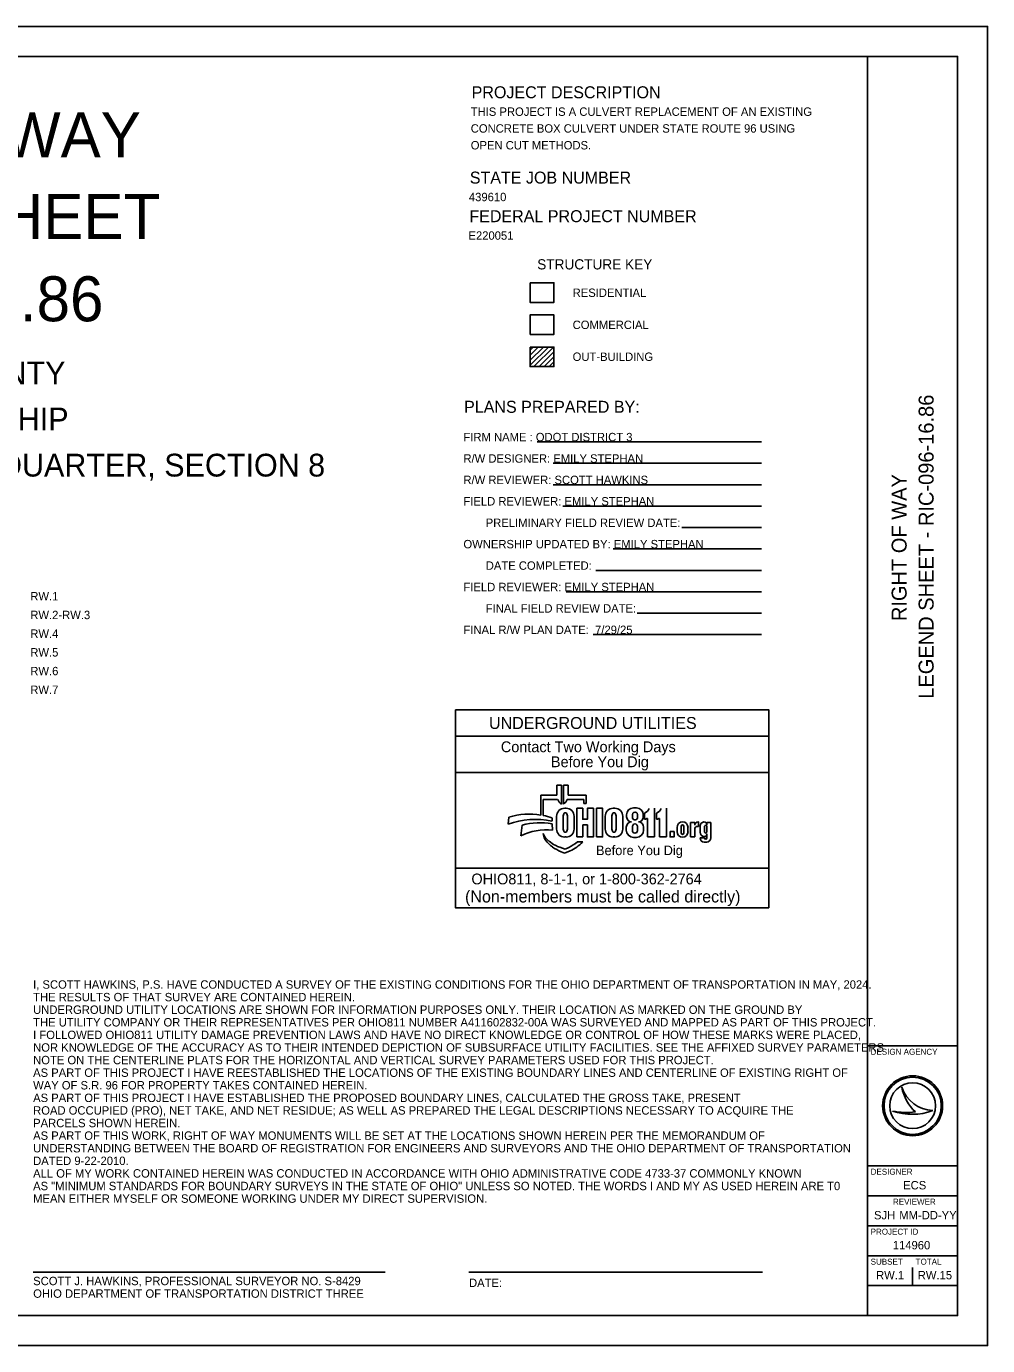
# Model space of a CAD drawing. Extents: x 0 to 34, y 0 to 22.
# Drawn here: x 17.97 to 34, y 0 to 22 of the extents above; entities that cross this region are included whole.
import ezdxf

# ---------------------------------------------------------------- set-up
doc = ezdxf.new("R2010")
doc.units = 0
for name, color, linetype in [('Default', 7, 'Continuous'), ('SC_Shading1', 7, 'Continuous'), ('SH_Border', 7, 'Continuous'), ('SH_Cut_Line', 7, 'Continuous'), ('SH_Data', 7, 'Continuous'), ('SH_Text', 7, 'Continuous')]:
    doc.layers.add(name, color=color, linetype=linetype)

msp = doc.modelspace()

# ---------------------------------------------------------------- linework, layer by layer
at = {"layer": 'Default'}
for p, q in [((18.087, 1.226), (23.954, 1.226)), ((25.349, 1.226), (30.249, 1.226))]:
    msp.add_line(p, q, dxfattribs=at)
at = {"layer": 'SC_Shading1'}
msp.add_lwpolyline([(26.372, 16.863), (26.769, 16.863), (26.769, 17.188), (26.372, 17.188)], close=True, dxfattribs=at)
at = {"layer": 'SH_Border'}
for p, q in [((32, 0.5), (32, 21.5)), ((32, 5), (33.5, 5)), ((32, 3), (33.5, 3)), ((32, 2.5), (33.5, 2.5)), ((32, 2), (33.5, 2)), ((32, 1.5), (33.5, 1.5)), ((32, 1), (33.5, 1))]:
    msp.add_line(p, q, dxfattribs=at)
msp.add_lwpolyline([(1.5, 21.5), (33.5, 21.5), (33.5, 0.5), (1.5, 0.5)], close=True, dxfattribs=at)
at = {"layer": 'SH_Cut_Line'}
msp.add_lwpolyline([(0, 0), (34, 0), (34, 22), (0, 22)], close=True, dxfattribs=at)
at = {"layer": 'SH_Data'}
for p, q in [((26.896, 9.349), (26.816, 9.349)), ((26.816, 9.349), (26.816, 9.182)), ((26.896, 9.032), (26.896, 9.349)), ((27.007, 9.349), (26.927, 9.349)), ((26.927, 9.349), (26.927, 9.032)), ((27.007, 9.182), (27.007, 9.349)), ((26.816, 9.182), (26.553, 9.182)), ((26.553, 9.182), (26.553, 8.848)), ((26.59, 8.841), (26.59, 9.105)), ((26.59, 9.105), (26.831, 9.105)), ((26.991, 9.105), (27.27, 9.105)), ((27.304, 9.182), (27.007, 9.182)), ((27.27, 9.105), (27.27, 9.042)), ((27.27, 9.042), (27.304, 9.042)), ((27.304, 9.042), (27.304, 9.182)), ((26.018, 8.814), (26.004, 8.697)), ((26.737, 8.746), (26.737, 8.804)), ((26.814, 8.827), (26.814, 8.615)), ((26.923, 8.632), (26.923, 8.815)), ((26.972, 8.961), (26.948, 8.961)), ((26.997, 8.815), (26.997, 8.632)), ((27.106, 8.615), (27.106, 8.827)), ((27.25, 8.96), (27.149, 8.96)), ((27.149, 8.96), (27.149, 8.482)), ((27.625, 8.827), (27.625, 8.615)), ((27.734, 8.632), (27.734, 8.815)), ((27.783, 8.961), (27.758, 8.961)), ((27.808, 8.815), (27.808, 8.632)), ((27.917, 8.615), (27.917, 8.827)), ((27.981, 8.854), (27.981, 8.817)), ((28.08, 8.8), (28.08, 8.859)), ((28.144, 8.968), (28.095, 8.968)), ((28.161, 8.859), (28.161, 8.8)), ((28.258, 8.817), (28.258, 8.854)), ((28.281, 8.779), (28.281, 8.881)), ((28.448, 8.96), (28.448, 8.482)), ((28.481, 8.779), (28.481, 8.881)), ((28.648, 8.96), (28.648, 8.482)), ((26.238, 8.678), (26.216, 8.499)), ((26.747, 8.595), (26.737, 8.701)), ((27.25, 8.482), (27.25, 8.684)), ((27.976, 8.647), (27.976, 8.596)), ((28.077, 8.587), (28.077, 8.649)), ((28.162, 8.649), (28.162, 8.587)), ((28.264, 8.596), (28.264, 8.647)), ((28.329, 8.482), (28.329, 8.793)), ((28.53, 8.482), (28.53, 8.793)), ((28.822, 8.573), (28.822, 8.64)), ((28.889, 8.571), (28.889, 8.64)), ((28.937, 8.64), (28.937, 8.571)), ((29.004, 8.64), (29.004, 8.573)), ((29.117, 8.725), (29.044, 8.725)), ((29.044, 8.725), (29.044, 8.482)), ((29.117, 8.678), (29.117, 8.725)), ((29.117, 8.482), (29.117, 8.609)), ((29.166, 8.658), (29.178, 8.658)), ((29.178, 8.733), (29.172, 8.733)), ((29.178, 8.658), (29.178, 8.733)), ((29.206, 8.56), (29.206, 8.664)), ((29.278, 8.574), (29.278, 8.65)), ((29.321, 8.68), (29.321, 8.726)), ((29.321, 8.726), (29.386, 8.726)), ((29.321, 8.65), (29.321, 8.574)), ((29.386, 8.726), (29.386, 8.468)), ((26.589, 8.542), (26.594, 8.515)), ((26.948, 8.482), (26.972, 8.482)), ((27.149, 8.482), (27.25, 8.482)), ((27.248, 8.402), (27.162, 8.402)), ((27.245, 8.399), (27.248, 8.402)), ((27.758, 8.482), (27.783, 8.482)), ((28.097, 8.475), (28.143, 8.475)), ((28.448, 8.482), (28.329, 8.482)), ((28.648, 8.482), (28.53, 8.482)), ((29.044, 8.482), (29.117, 8.482)), ((29.206, 8.468), (29.278, 8.468)), ((29.316, 8.398), (29.276, 8.398)), ((29.321, 8.468), (29.321, 8.537)), ((26.954, 8.281), (26.866, 8.311)), ((26.89, 8.235), (26.945, 8.211)), ((26.945, 8.211), (27.04, 8.252)), ((27.016, 8.307), (26.954, 8.281)), ((30.352, 7.303), (25.127, 7.303)), ((32.567, 4.31), (32.567, 4.31)), ((32.75, 4), (32.75, 4)), ((32.417, 3.91), (32.417, 3.91)), ((33.087, 3.919), (33.087, 3.919)), ((32.75, 1), (32.75, 1.3))]:
    msp.add_line(p, q, dxfattribs=at)
for points in [[(25.127, 10.603), (30.352, 10.603), (30.352, 10.163), (25.127, 10.163)], [(25.127, 10.163), (30.352, 10.163), (30.352, 9.558), (25.127, 9.558)], [(25.127, 9.558), (30.352, 9.558), (30.352, 7.963), (25.127, 7.963)], [(28.706, 8.571), (28.772, 8.571), (28.772, 8.482), (28.706, 8.482)], [(25.127, 7.963), (30.352, 7.963), (30.352, 7.303), (25.127, 7.303)]]:
    msp.add_lwpolyline(points, close=True, dxfattribs=at)
for points in [[(27.25, 8.684), (27.326, 8.684), (27.326, 8.482), (27.428, 8.482), (27.428, 8.96), (27.326, 8.96), (27.326, 8.779), (27.25, 8.779), (27.25, 8.96)], [(27.479, 8.482), (27.581, 8.482), (27.581, 8.96), (27.479, 8.96), (27.479, 8.482)], [(28.062, 8.734), (28.062, 8.734)], [(28.178, 8.734), (28.178, 8.734)]]:
    msp.add_lwpolyline(points, dxfattribs=at)
for radius in [0.5, 0.477, 0.477, 0.382]:
    msp.add_circle((32.75, 4), radius, dxfattribs=at)
for centre, radius, start, end in [((26.968, 9.16), 0.147, 201.9296, 240.7469), ((26.855, 9.16), 0.147, 299.2531, 338.0704), ((26.361, 7.639), 1.224, 81.0007, 106.3144), ((26.361, 7.639), 1.224, 72.1402, 79.2074), ((26.948, 8.827), 0.134, 90, 180), ((26.972, 8.827), 0.134, 0, 90), ((27.758, 8.827), 0.134, 90, 180), ((27.783, 8.827), 0.134, 0, 90), ((28.095, 8.854), 0.114, 90, 180), ((28.065, 8.817), 0.0837, 180, 268.1442), ((28.144, 8.854), 0.114, 0, 90), ((28.175, 8.817), 0.0837, 272.2058, 0), ((28.231, 9.003), 0.132, 292.5572, 340.7355), ((28.431, 9.003), 0.132, 292.5572, 340.7355), ((26.455, 7.444), 1.332, 77.8238, 109.8274), ((26.644, 7.651), 0.95, 83.8248, 116.8021), ((26.537, 7.626), 1.094, 79.44, 105.8467), ((26.948, 8.615), 0.134, 180, 270), ((26.972, 8.615), 0.134, 270, 0), ((27.758, 8.615), 0.134, 180, 270), ((27.783, 8.615), 0.134, 270, 0), ((28.062, 8.647), 0.0865, 90, 180), ((28.097, 8.596), 0.121, 180, 270), ((28.143, 8.596), 0.121, 270, 0), ((28.178, 8.647), 0.0865, 0, 90), ((28.269, 8.911), 0.132, 275.1733, 297.0931), ((28.469, 8.911), 0.132, 275.1733, 297.0931), ((28.917, 8.64), 0.0956, 92.5886, 180), ((28.909, 8.64), 0.0956, 0, 87.4114), ((29.172, 8.678), 0.0548, 90, 180), ((29.166, 8.609), 0.0493, 90, 180), ((29.274, 8.664), 0.0686, 92.6865, 180), ((29.268, 8.68), 0.0524, 0, 86.9262), ((26.869, 8.649), 0.3, 201.0457, 232.5314), ((26.805, 8.551), 0.214, 189.6817, 216.0884), ((27.005, 8.697), 0.461, 216.0884, 235.7167), ((27.157, 9.025), 0.773, 232.5314, 241.794), ((26.801, 8.801), 0.538, 293.4582, 312.0712), ((26.801, 8.801), 0.599, 293.4582, 317.8286), ((28.917, 8.573), 0.0956, 180, 267.4114), ((28.909, 8.573), 0.0956, 272.5886, 0), ((29.275, 8.56), 0.0692, 180, 265.7132), ((29.276, 8.468), 0.0699, 180, 270), ((29.274, 8.537), 0.0467, 264.7825, 0), ((29.316, 8.468), 0.0699, 270, 0), ((27.253, 9.061), 0.903, 235.7167, 246.2325), ((27.03, 8.788), 0.504, 241.794, 250.9821), ((33.116, 4.498), 0.58, 198.9257, 198.9319), ((33.347, 4.47), 0.796, 191.6379, 191.6421), ((33.116, 4.498), 0.58, 198.9319, 267.1657), ((33.347, 4.47), 0.796, 191.6421, 226.0947), ((32.739, 4.87), 1.013, 251.4576, 290.0832), ((32.648, 5.154), 1.266, 259.4964, 259.4995), ((32.739, 4.87), 1.013, 251.4527, 251.4576), ((32.648, 5.154), 1.266, 259.4995, 276.6672)]:
    msp.add_arc(centre, radius, start, end, dxfattribs=at)
for centre, major_axis, ratio, start_param, end_param in [((26.96, 8.815), (0, 0.0723), 0.514403, 4.712389, 7.853982), ((27.771, 8.815), (0, 0.0723), 0.514403, 4.712389, 7.853982), ((28.121, 8.859), (0.0404, 0), 0.969373, 0, 3.141593), ((28.121, 8.8), (0.0404, 0), 0.818453, 3.141593, 6.283185), ((26.96, 8.632), (0, 0.0723), 0.514403, 1.570796, 4.712389), ((27.771, 8.632), (0, 0.0723), 0.514403, 1.570796, 4.712389), ((28.119, 8.649), (0, 0.0535), 0.794529, 4.712389, 7.853982), ((28.119, 8.587), (0.0425, 0), 0.959837, 3.141593, 6.283185), ((28.913, 8.64), (0, 0.0434), 0.553236, 4.712389, 7.853982), ((29.299, 8.65), (0, 0.0275), 0.777179, 4.712389, 7.853982), ((28.913, 8.571), (0, 0.046), 0.522014, 1.570796, 4.712389), ((29.299, 8.574), (0, 0.0275), 0.777179, 1.570796, 4.712389), ((29.299, 8.468), (0.0214, 0), 0.959012, 3.141593, 6.283185)]:
    msp.add_ellipse(centre, major_axis=major_axis, ratio=ratio, start_param=start_param, end_param=end_param, dxfattribs=at)
at = {"layer": 'SH_Text'}
for p, q in [((26.372, 16.652), (26.373, 16.653)), ((26.372, 16.602), (26.424, 16.653)), ((26.372, 16.517), (26.508, 16.653)), ((26.372, 16.432), (26.593, 16.653)), ((26.372, 16.348), (26.678, 16.653)), ((26.436, 16.327), (26.762, 16.653)), ((26.521, 16.327), (26.769, 16.575)), ((26.372, 16.332), (26.377, 16.327)), ((26.606, 16.327), (26.769, 16.491)), ((26.691, 16.327), (26.769, 16.406)), ((26.491, 15.071), (30.229, 15.071)), ((26.756, 14.714), (30.229, 14.714)), ((26.756, 14.357), (30.229, 14.357)), ((26.92, 14), (30.229, 14)), ((28.901, 13.642), (30.229, 13.642)), ((27.756, 13.286), (30.229, 13.286)), ((27.47, 12.928), (30.229, 12.928)), ((26.973, 12.571), (30.229, 12.571)), ((28.154, 12.214), (30.229, 12.214)), ((27.425, 11.857), (30.229, 11.857))]:
    msp.add_line(p, q, dxfattribs=at)
for points in [[(26.372, 17.724), (26.769, 17.724), (26.769, 17.398), (26.372, 17.398)], [(26.372, 16.653), (26.769, 16.653), (26.769, 16.327), (26.372, 16.327)]]:
    msp.add_lwpolyline(points, close=True, dxfattribs=at)

# ---------------------------------------------------------------- texts
at = {"layer": 'Default'}
for s, p in [('I, SCOTT HAWKINS, P.S. HAVE CONDUCTED A SURVEY OF THE EXISTING CONDITIONS FOR THE OHIO DEPARTMENT OF TRANSPORTATION IN MAY, 2024.', (18.085, 5.952)), ('THE RESULTS OF THAT SURVEY ARE CONTAINED HEREIN.', (18.085, 5.742)), ('UNDERGROUND UTILITY LOCATIONS ARE SHOWN FOR INFORMATION PURPOSES ONLY. THEIR LOCATION AS MARKED ON THE GROUND BY', (18.085, 5.532)), ('THE UTILITY COMPANY OR THEIR REPRESENTATIVES PER OHIO811 NUMBER A411602832-00A WAS SURVEYED AND MAPPED AS PART OF THIS PROJECT.', (18.085, 5.322)), ('I FOLLOWED OHIO811 UTILITY DAMAGE PREVENTION LAWS AND HAVE NO DIRECT KNOWLEDGE OR CONTROL OF HOW THESE MARKS WERE PLACED,', (18.085, 5.112)), ('NOR KNOWLEDGE OF THE ACCURACY AS TO THEIR INTENDED DEPICTION OF SUBSURFACE UTILITY FACILITIES. SEE THE AFFIXED SURVEY PARAMETERS', (18.085, 4.902)), ('AS PART OF THIS PROJECT I HAVE REESTABLISHED THE LOCATIONS OF THE EXISTING BOUNDARY LINES AND CENTERLINE OF EXISTING RIGHT OF', (18.085, 4.482)), ('NOTE ON THE CENTERLINE PLATS FOR THE HORIZONTAL AND VERTICAL SURVEY PARAMETERS USED FOR THIS PROJECT.', (18.085, 4.692)), ('WAY OF S.R. 96 FOR PROPERTY TAKES CONTAINED HEREIN.', (18.085, 4.272)), ('AS PART OF THIS PROJECT I HAVE ESTABLISHED THE PROPOSED BOUNDARY LINES, CALCULATED THE GROSS TAKE, PRESENT', (18.085, 4.062)), ('ROAD OCCUPIED (PRO), NET TAKE, AND NET RESIDUE; AS WELL AS PREPARED THE LEGAL DESCRIPTIONS NECESSARY TO ACQUIRE THE', (18.085, 3.852)), ('PARCELS SHOWN HEREIN.', (18.085, 3.642)), ('AS PART OF THIS WORK, RIGHT OF WAY MONUMENTS WILL BE SET AT THE LOCATIONS SHOWN HEREIN PER THE MEMORANDUM OF', (18.085, 3.432)), ('UNDERSTANDING BETWEEN THE BOARD OF REGISTRATION FOR ENGINEERS AND SURVEYORS AND THE OHIO DEPARTMENT OF TRANSPORTATION', (18.085, 3.222)), ('DATED 9-22-2010.', (18.085, 3.012)), ('ALL OF MY WORK CONTAINED HEREIN WAS CONDUCTED IN ACCORDANCE WITH OHIO ADMINISTRATIVE CODE 4733-37 COMMONLY KNOWN', (18.085, 2.802)), ('AS "MINIMUM STANDARDS FOR BOUNDARY SURVEYS IN THE STATE OF OHIO" UNLESS SO NOTED. THE WORDS I AND MY AS USED HEREIN ARE T0', (18.085, 2.592)), ('MEAN EITHER MYSELF OR SOMEONE WORKING UNDER MY DIRECT SUPERVISION. ', (18.085, 2.382)), ('SCOTT J. HAWKINS, PROFESSIONAL SURVEYOR NO. S-8429', (18.086, 1.008)), ('DATE:', (25.353, 0.977)), ('OHIO DEPARTMENT OF TRANSPORTATION DISTRICT THREE', (18.086, 0.798))]:
    msp.add_text(s, height=0.14, dxfattribs=at).set_placement(p)
at = {"layer": 'SH_Data'}
for s, height, p in [('RIGHT OF WAY', 0.75, (12.527, 19.816)), ('LEGEND SHEET', 0.75, (12.458, 18.457)), ('RIC-096-16.86', 0.75, (12.68, 17.082)), ('    RICHLAND COUNTY    ', 0.38, (13.175, 16.03)), ('    WELLER TOWNSHIP    ', 0.38, (13.143, 15.262)), ('        SW QUARTER, SECTION 5; NW QUARTER, SECTION 8        ', 0.38, (8.696, 14.493)), ('RW.1  ', 0.14, (18.038, 12.427)), ('RW.2-RW.3 ', 0.14, (18.038, 12.115)), ('RW.4  ', 0.14, (18.038, 11.803)), ('RW.5  ', 0.14, (18.038, 11.491)), ('RW.6  ', 0.14, (18.038, 11.179)), ('RW.7  ', 0.14, (18.038, 10.867)), ('UNDERGROUND UTILITIES', 0.2, (25.686, 10.283)), ('Contact Two Working Days', 0.18, (25.884, 9.896)), ('Before You Dig', 0.18, (26.719, 9.646)), ('Before You Dig', 0.15972, (27.47, 8.179)), ('OHIO811, 8-1-1, or 1-800-362-2764', 0.18, (25.393, 7.692)), ('(Non-members must be called directly)', 0.2, (25.287, 7.39)), ('DESIGN AGENCY', 0.1, (32.05, 4.85)), ('DESIGNER', 0.1, (32.05, 2.85)), ('ECS', 0.14, (32.592, 2.605)), ('REVIEWER', 0.1, (32.422, 2.35)), ('SJH', 0.14, (32.105, 2.105)), ('MM-DD-YY', 0.14, (32.527, 2.105)), ('PROJECT ID', 0.1, (32.05, 1.85)), ('114960', 0.14, (32.419, 1.605)), ('SUBSET', 0.1, (32.05, 1.35)), ('TOTAL', 0.1, (32.8, 1.35)), ('RW.1', 0.14, (32.14, 1.105)), ('RW.15', 0.14, (32.835, 1.105))]:
    msp.add_text(s, height=height, dxfattribs=at).set_placement(p)
for s, p in [('LEGEND SHEET - RIC-096-16.86', (33.1, 10.787)), ('RIGHT OF WAY', (32.65, 12.082))]:
    msp.add_text(s, height=0.25, rotation=90, dxfattribs=at).set_placement(p)
at = {"layer": 'SH_Text'}
for s, height, p in [('PROJECT DESCRIPTION', 0.2, (25.397, 20.801)), ('THIS PROJECT IS A CULVERT REPLACEMENT OF AN EXISTING        ', 0.14, (25.382, 20.508)), ('CONCRETE BOX CULVERT UNDER STATE ROUTE 96 USING             ', 0.14, (25.382, 20.228)), ('OPEN CUT METHODS.                          ', 0.14, (25.382, 19.948)), ('STATE JOB NUMBER', 0.2, (25.366, 19.378)), ('439610                                                                ', 0.14, (25.351, 19.085)), ('FEDERAL PROJECT NUMBER', 0.2, (25.359, 18.735)), ('E220051                                                               ', 0.14, (25.344, 18.442)), ('STRUCTURE KEY', 0.17, (26.49, 17.947)), ('RESIDENTIAL', 0.14, (27.081, 17.488)), ('COMMERCIAL', 0.14, (27.081, 16.953)), ('OUT-BUILDING', 0.14, (27.081, 16.421)), ('PLANS PREPARED BY:', 0.2, (25.271, 15.556)), ('FIRM NAME : ODOT DISTRICT 3', 0.14, (25.26, 15.081)), ('R/W DESIGNER: EMILY STEPHAN', 0.14, (25.26, 14.724)), ('R/W REVIEWER: SCOTT HAWKINS', 0.14, (25.26, 14.367)), ('FIELD REVIEWER: EMILY STEPHAN', 0.14, (25.26, 14.01)), ('PRELIMINARY FIELD REVIEW DATE:', 0.14, (25.632, 13.652)), ('OWNERSHIP UPDATED BY: EMILY STEPHAN', 0.14, (25.26, 13.296)), ('DATE COMPLETED:', 0.14, (25.632, 12.938)), ('FIELD REVIEWER: EMILY STEPHAN', 0.14, (25.26, 12.581)), ('FINAL FIELD REVIEW DATE:', 0.14, (25.632, 12.224)), ('FINAL R/W PLAN DATE:  7/29/25', 0.14, (25.26, 11.867))]:
    msp.add_text(s, height=height, dxfattribs=at).set_placement(p)

doc.saveas('drawing.dxf')
